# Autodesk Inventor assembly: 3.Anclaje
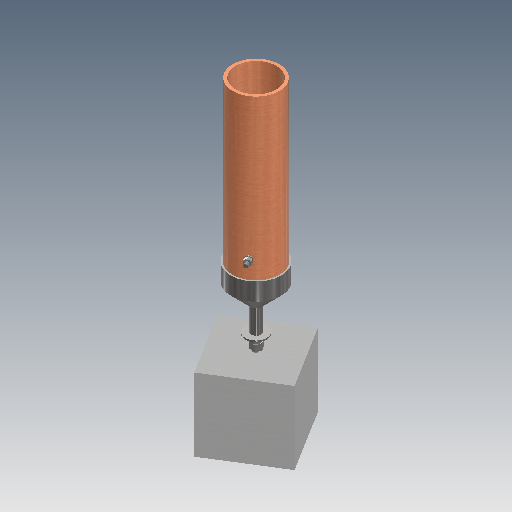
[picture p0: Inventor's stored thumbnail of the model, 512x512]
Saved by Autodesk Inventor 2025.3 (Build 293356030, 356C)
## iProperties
Created: 2025-10
Part Number: 3.Anclaje
Document SubType Name: Assembly
Designer: User
Author: User
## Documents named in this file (10)
- C:\Users\User\OneDrive - Institucion Universitaria Colegio Mayor de Antioquia\Escritorio\PROTECTO INV\Anclajes Profesor\6. Anclaje de Pernos\3.Anclaje.iam
- C:\Users\User\OneDrive - Institucion Universitaria Colegio Mayor de Antioquia\Escritorio\PROTECTO INV\Anclajes Profesor\6. Anclaje de Pernos\1.Barra horizontal 12mm.ipt
- C:\Users\User\OneDrive - Institucion Universitaria Colegio Mayor de Antioquia\Escritorio\PROTECTO INV\Anclajes Profesor\6. Anclaje de Pernos\2.Perfil de hierro.ipt
- C:\Users\User\OneDrive - Institucion Universitaria Colegio Mayor de Antioquia\Escritorio\PROTECTO INV\Anclajes Profesor\6. Anclaje de Pernos\3.Barra Vertical 20mm.ipt
- C:\Users\User\OneDrive - Institucion Universitaria Colegio Mayor de Antioquia\Escritorio\PROTECTO INV\Anclajes Profesor\6. Anclaje de Pernos\4.Bloque concreto.ipt
- C:\Users\User\OneDrive - Institucion Universitaria Colegio Mayor de Antioquia\Escritorio\PROTECTO INV\Anclajes Profesor\6. Anclaje de Pernos\0.Guadua.ipt
- C:\Users\User\OneDrive - Institucion Universitaria Colegio Mayor de Antioquia\Documentos\Inventor\Content Center Files\R2025\es-ES\ANSI B18.22 M\ANSI B18.22M - 12 N.ipt
- C:\Users\User\OneDrive - Institucion Universitaria Colegio Mayor de Antioquia\Escritorio\PROTECTO INV\Anclajes Profesor\6. Anclaje de Pernos\7.Tuerca 20mm.ipt
- C:\Users\User\OneDrive - Institucion Universitaria Colegio Mayor de Antioquia\Escritorio\PROTECTO INV\Anclajes Profesor\6. Anclaje de Pernos\8.Relleno de concreto.ipt
- C:\Users\User\OneDrive - Institucion Universitaria Colegio Mayor de Antioquia\Escritorio\PROTECTO INV\Anclajes Profesor\6. Anclaje de Pernos\5.Tuerca 12mm.ipt
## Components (12 placed, 9 different names)
1. 1.Barra horizontal 12mm:1 — Coincidencia:2, Rígido:1, Coincidencia:18, Coincidencia:20
2. 2.Perfil de hierro:1 — Coincidencia:1, Coincidencia:3, Rígido:3, Coincidencia:16, Rígido:4
3. 3.Barra Vertical 20mm:1 — Coincidencia:1, Coincidencia:2, Rígido:1, Rígido:2, Coincidencia:10, Coincidencia:15, Coincidencia:24
4. 4.Bloque concreto:1 — Rígido:2, Coincidencia:3
5. 0.Guadua:1 — Rígido:3
6. Arandela plana (Métrico) 12 N:1 — Coincidencia:10, Coincidencia:19
7. AS 1252 - Métrico M20:3 — Coincidencia:15, Coincidencia:16, Coincidencia:22
8. 8.Relleno de concreto:1 — Rígido:4
9. AS 1252 - Métrico M12:3 — Coincidencia:18, Coincidencia:19
10. AS 1252 - Métrico M12:4 — Coincidencia:20, Coincidencia:25
11. AS 1252 - Métrico M20:4 — Coincidencia:22
12. Arandela plana (Métrico) 12 N:2 — Coincidencia:24, Coincidencia:25
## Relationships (16: Mate 12, WeldJoint 4)
- Coincidencia:1 [Mate]: 2.Perfil de hierro:1 ↔ 3.Barra Vertical 20mm:1
- Coincidencia:2 [Mate]: 1.Barra horizontal 12mm:1 ↔ 3.Barra Vertical 20mm:1
- Rígido:1 [WeldJoint]: 1.Barra horizontal 12mm:1 ↔ 3.Barra Vertical 20mm:1
- Rígido:2 [WeldJoint]: 3.Barra Vertical 20mm:1 ↔ 4.Bloque concreto:1
- Coincidencia:3 [Mate]: 2.Perfil de hierro:1 ↔ 4.Bloque concreto:1
- Rígido:3 [WeldJoint]: 2.Perfil de hierro:1 ↔ 0.Guadua:1
- Coincidencia:10 [Mate]: 3.Barra Vertical 20mm:1 ↔ Arandela plana (Métrico) 12 N:1
- Coincidencia:15 [Mate]: 3.Barra Vertical 20mm:1 ↔ AS 1252 - Métrico M20:3
- Coincidencia:16 [Mate]: 2.Perfil de hierro:1 ↔ AS 1252 - Métrico M20:3
- Rígido:4 [WeldJoint]: 2.Perfil de hierro:1 ↔ 8.Relleno de concreto:1
- Coincidencia:18 [Mate]: 1.Barra horizontal 12mm:1 ↔ AS 1252 - Métrico M12:3
- Coincidencia:19 [Mate]: Arandela plana (Métrico) 12 N:1 ↔ AS 1252 - Métrico M12:3
- Coincidencia:20 [Mate]: 1.Barra horizontal 12mm:1 ↔ AS 1252 - Métrico M12:4
- Coincidencia:22 [Mate]: AS 1252 - Métrico M20:3 ↔ AS 1252 - Métrico M20:4
- Coincidencia:24 [Mate]: 3.Barra Vertical 20mm:1 ↔ Arandela plana (Métrico) 12 N:2
- Coincidencia:25 [Mate]: AS 1252 - Métrico M12:4 ↔ Arandela plana (Métrico) 12 N:2
